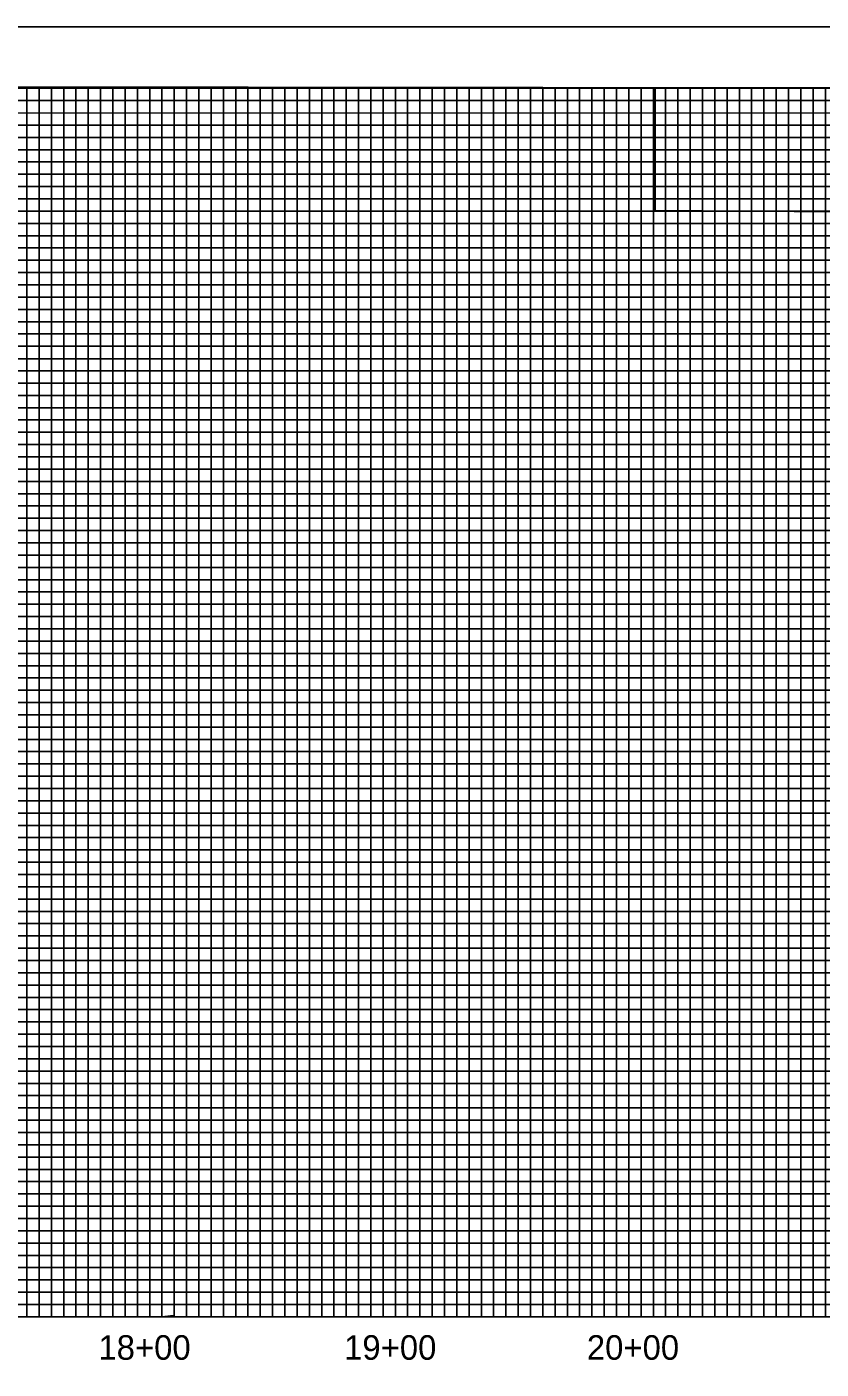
# Model space of a CAD drawing. Extents: x 505602 to 507548, y 483109 to 484209.
# Drawn here: x 506569 to 506892, y 483662 to 484209 of the extents above; entities that cross this region are included whole.
import ezdxf

# ---------------------------------------------------------------- set-up
doc = ezdxf.new("R2010")
doc.units = 0
for name, color, linetype in [('Exist Vertical Profile Vertical Axis Label', 7, 'Continuous'), ('Scratch_Level_5', 7, 'Continuous'), ('Sheet Layout Profile Border Port 1', 7, 'Continuous'), ('Sheet Plot Border Outside CELL', 7, 'Continuous'), ('Sheet Profile CELL', 7, 'Continuous'), ('Sheet Profile Grid Major CELL', 7, 'Continuous'), ('Sheet Profile Grid Middle CELL', 7, 'Continuous'), ('Sheet Profile Grid Minor CELL', 7, 'Continuous')]:
    doc.layers.add(name, color=color, linetype=linetype)

msp = doc.modelspace()

# ---------------------------------------------------------------- linework, layer by layer
at = {"layer": 'Scratch_Level_5'}
msp.add_lwpolyline([(505819.08, 484183.83), (506824.84, 484183.83), (506824.84, 484134), (506919.08, 484133.22), (506919.3, 483683.71), (505819.08, 483683.71)], close=True, dxfattribs=at)
msp.add_lwpolyline([(505819.08, 484022.66), (505819.08, 483683.71), (507219.08, 483683.71), (507219.08, 484022.66)], dxfattribs=at)
at = {"layer": 'Sheet Layout Profile Border Port 1'}
msp.add_lwpolyline([(505819.08, 484185.09), (505819.08, 483683.71), (507019.08, 483683.71), (507019.08, 484183.71), (507019.08, 484183.71), (507019.08, 484183.71)], close=True, dxfattribs=at)
at = {"layer": 'Sheet Plot Border Outside CELL'}
msp.add_lwpolyline([(505602.08, 483108.71), (507286.08, 483108.71), (507286.08, 484208.71), (505602.08, 484208.71)], close=True, dxfattribs=at)
at = {"layer": 'Sheet Profile CELL'}
msp.add_line((505769.08, 483683.71), (507269.08, 483683.71), dxfattribs=at)
msp.add_lwpolyline([(507269.08, 484183.71), (505769.08, 484183.71), (505769.08, 483133.71), (507269.08, 483133.71)], close=True, dxfattribs=at)
at = {"layer": 'Sheet Profile Grid Major CELL'}
for points in [[(506519.08, 483683.71), (506569.08, 483683.71), (506569.08, 484183.71), (506619.08, 484183.71), (506619.08, 483683.71), (506669.08, 483683.71), (506669.08, 484183.71), (506719.08, 484183.71), (506719.08, 483683.71), (506769.08, 483683.71), (506769.08, 484183.71), (506819.08, 484183.71), (506819.08, 483683.71), (506869.08, 483683.71), (506869.08, 484183.71), (506919.08, 484183.71), (506919.08, 483683.71), (506969.08, 483683.71), (506969.08, 484183.71), (507019.08, 484183.71), (507019.08, 483683.71), (507069.08, 483683.71), (507069.08, 484183.71), (507095.38, 484183.71)], [(505769.08, 484133.71), (507069.08, 484133.71)], [(507069.08, 484083.71), (505769.08, 484083.71), (505769.08, 484033.71), (507069.08, 484033.71)], [(507269.08, 483983.71), (505769.08, 483983.71), (505769.08, 483933.71), (507269.08, 483933.71)], [(507269.08, 483883.71), (505769.08, 483883.71), (505769.08, 483833.71), (507269.08, 483833.71)], [(507269.08, 483783.71), (505769.08, 483783.71), (505769.08, 483783.71), (505769.08, 483733.71), (507269.08, 483733.71)]]:
    msp.add_lwpolyline(points, dxfattribs=at)
at = {"layer": 'Sheet Profile Grid Middle CELL'}
msp.add_line((505769.08, 484158.71), (507069.03, 484158.71), dxfattribs=at)
for points in [[(506544.08, 483683.71), (506594.08, 483683.71), (506594.08, 484183.71), (506644.08, 484183.71), (506644.08, 483683.71), (506694.08, 483683.71), (506694.08, 484183.71), (506744.08, 484183.71), (506744.08, 483683.71), (506794.08, 483683.71), (506794.08, 484183.71), (506844.08, 484183.71), (506844.08, 483683.71), (506894.08, 483683.71), (506894.08, 484183.71), (506944.08, 484183.71), (506944.08, 483683.71), (506994.08, 483683.71), (506994.08, 484183.71), (507044.08, 484183.71), (507044.08, 483683.71), (507094.08, 483683.71), (507094.08, 484022.66)], [(507069.08, 484108.71), (505769.08, 484108.71), (505769.08, 484058.71), (507069.08, 484058.71)], [(507269.08, 484008.71), (505769.08, 484008.71), (505769.08, 483958.71), (507094.08, 483958.71)], [(507269.08, 483908.71), (505769.08, 483908.71), (505769.08, 483858.71), (507269.08, 483858.71)], [(507269.08, 483808.71), (505769.08, 483808.71), (505769.08, 483758.71), (507269.08, 483758.71)], [(507269.08, 483708.71), (505769.08, 483708.71)]]:
    msp.add_lwpolyline(points, dxfattribs=at)
at = {"layer": 'Sheet Profile Grid Minor CELL'}
for p, q in [((505819.08, 484178.71), (507069.08, 484178.71)), ((507069.08, 484173.71), (505819.08, 484173.36)), ((505819.08, 484168.71), (507069.08, 484168.71)), ((507069.03, 484048.71), (505819.08, 484048.71)), ((507069.08, 484043.71), (505819.08, 484043.71)), ((507069.08, 484038.71), (505819.08, 484038.71)), ((505819.08, 484028.71), (507069.08, 484028.71)), ((507069.08, 484023.71), (505819.08, 484023.71)), ((505819.08, 484018.71), (507219.08, 484018.71)), ((507219.08, 483998.71), (505819.08, 483998.71)), ((505819.08, 483993.71), (507219.08, 483993.71)), ((507219.08, 483973.71), (505819.08, 483973.71)), ((505819.08, 483968.71), (507219.08, 483968.71)), ((507219.08, 483948.71), (505819.08, 483948.71)), ((505819.08, 483943.71), (507219.08, 483943.71)), ((507219.08, 483938.71), (505819.08, 483938.71)), ((505819.08, 483928.71), (507219.08, 483928.71)), ((507219.08, 483923.71), (505819.08, 483923.71)), ((505819.08, 483918.71), (507219.08, 483918.71)), ((507219.08, 483913.71), (505819.08, 483913.71)), ((505819.08, 483903.71), (507219.08, 483903.71)), ((507219.08, 483898.71), (505819.08, 483898.71)), ((505819.08, 483893.71), (507219.08, 483893.71)), ((507219.08, 483888.71), (505819.08, 483888.71)), ((505819.08, 483878.71), (507219.08, 483878.71)), ((507219.08, 483873.71), (505819.08, 483873.71)), ((505819.08, 483868.71), (507219.08, 483868.71)), ((507219.08, 483863.71), (505819.08, 483863.71)), ((505819.08, 483853.71), (507219.08, 483853.71)), ((507219.08, 483848.71), (505819.08, 483848.71)), ((505819.08, 483843.71), (507219.08, 483843.71)), ((507219.08, 483838.71), (505819.08, 483838.71)), ((505819.08, 483828.71), (507219.08, 483828.71)), ((507219.08, 483823.71), (505819.08, 483823.71)), ((505819.08, 483818.71), (507219.08, 483818.71)), ((507219.08, 483813.71), (505819.08, 483813.71)), ((505819.08, 483803.71), (507219.08, 483803.71)), ((507219.08, 483798.71), (505819.08, 483798.71)), ((507219.08, 483793.71), (505819.08, 483793.71)), ((507219.08, 483788.71), (505819.08, 483788.71)), ((505819.08, 483778.71), (507219.08, 483778.71)), ((507219.08, 483773.71), (505819.08, 483773.71)), ((505819.08, 483768.71), (507219.08, 483768.71)), ((507219.08, 483763.71), (505819.08, 483763.71)), ((505819.08, 483753.71), (507219.08, 483753.71)), ((507219.08, 483748.71), (505819.08, 483748.71)), ((505819.08, 483743.71), (507219.08, 483743.71)), ((507219.08, 483738.71), (505819.08, 483738.71)), ((505819.08, 483728.71), (507219.08, 483728.71)), ((507219.08, 483723.71), (505819.08, 483723.71)), ((505819.08, 483718.71), (507219.08, 483718.71)), ((507219.08, 483713.71), (505819.08, 483713.71)), ((505819.08, 483703.71), (507219.08, 483703.71)), ((507219.08, 483698.71), (505819.08, 483698.71)), ((505819.08, 483693.71), (507219.08, 483693.71))]:
    msp.add_line(p, q, dxfattribs=at)
for points in [[(506564.08, 484183.71), (506574.08, 484183.71), (506574.08, 483683.71), (506579.08, 483683.71), (506579.08, 484183.71), (506584.08, 484183.71), (506584.08, 483683.71), (506589.08, 483683.71), (506589.08, 484183.71), (506599.08, 484183.71), (506599.08, 483683.71), (506604.08, 483683.71), (506604.08, 484183.71), (506609.08, 484183.71), (506609.08, 483683.71), (506614.08, 483683.71), (506614.08, 484183.71), (506624.08, 484183.71), (506624.08, 483683.71), (506628.78, 483684.26), (506629.08, 483683.71), (506629.08, 484183.71), (506634.08, 484183.71), (506634.08, 483683.71), (506639.08, 483683.71), (506639.08, 484183.71), (506649.08, 484183.71), (506649.08, 483683.71), (506654.08, 483683.71)], [(506654.08, 483683.71), (506654.08, 484183.71), (506659.08, 484183.71), (506659.08, 483683.71), (506664.08, 483683.71), (506664.08, 484183.71), (506674.08, 484183.71), (506674.08, 483683.71), (506679.08, 483683.71), (506679.08, 484183.71), (506684.08, 484183.71), (506684.08, 483683.71), (506689.08, 483683.71), (506689.08, 484183.71), (506699.08, 484183.71), (506699.08, 483683.71), (506704.08, 483683.71), (506704.08, 484183.71), (506709.08, 484183.71), (506709.08, 483683.71), (506714.08, 483683.71), (506714.08, 484183.71), (506724.08, 484183.71), (506724.08, 483683.71), (506729.08, 483683.71), (506729.08, 484183.71), (506734.08, 484183.71), (506734.08, 483683.71), (506739.08, 483683.71), (506739.08, 484183.71), (506749.08, 484183.71), (506749.08, 483683.71), (506754.08, 483683.71), (506754.08, 484183.71), (506759.08, 484183.71), (506759.08, 483683.71), (506764.08, 483683.71), (506764.08, 484183.71), (506774.08, 484183.71), (506774.08, 483683.71), (506779.08, 483683.71), (506779.08, 484183.71), (506784.08, 484183.71), (506784.08, 483683.71), (506789.08, 483683.71), (506789.08, 484183.71), (506799.08, 484183.71), (506799.08, 483683.71), (506804.08, 483683.71), (506804.08, 484183.71), (506809.08, 484183.71), (506809.08, 483683.71), (506814.08, 483683.71), (506814.08, 484183.71), (506824.08, 484183.71), (506824.08, 483683.71), (506829.08, 483683.71), (506829.08, 484183.71), (506834.08, 484183.71), (506834.08, 483683.71), (506839.08, 483683.71), (506839.08, 484183.71), (506849.08, 484183.71), (506849.08, 483683.71), (506854.08, 483683.71), (506854.08, 484183.71), (506859.08, 484183.71), (506859.08, 483683.71), (506864.08, 483683.71), (506864.08, 484183.71), (506874.08, 484183.71), (506874.08, 483683.71), (506879.08, 483683.71), (506879.08, 484183.71), (506884.08, 484183.71), (506884.08, 483683.71), (506889.08, 483683.71), (506889.08, 484183.71), (506899.08, 484183.71)], [(507069.08, 484163.71), (505819.08, 484163.71), (505819.08, 484153.71), (507069.08, 484153.71)], [(507069.03, 484148.71), (505819.08, 484148.71), (505819.08, 484143.71), (507069.08, 484143.71)], [(507069.08, 484138.71), (505819.08, 484138.71), (505819.08, 484128.71), (507069.08, 484128.71)], [(507069.08, 484123.71), (505819.08, 484123.71), (505819.08, 484118.71), (507069.08, 484118.71)], [(507069.08, 484113.71), (505819.08, 484113.71), (505819.08, 484103.71), (507069.08, 484103.71)], [(507069.08, 484098.71), (505819.08, 484098.71), (505819.08, 484093.71), (507069.08, 484093.71)], [(507069.08, 484088.71), (505819.08, 484088.71), (505819.08, 484078.71), (507069.08, 484078.71)], [(507069.08, 484073.61), (505819.18, 484073.61), (505819.18, 484068.71), (507069.08, 484068.71)], [(507069.08, 484063.71), (505819.08, 484063.71), (505819.08, 484053.71), (507069.08, 484053.71)], [(507219.08, 484013.71), (505819.08, 484013.71), (505819.08, 484003.71), (507219.08, 484003.71)], [(507219.08, 483988.71), (505819.08, 483988.71), (505819.08, 483978.71), (507219.08, 483978.71)], [(507219.08, 483963.71), (505819.08, 483963.71), (505819.08, 483953.71), (507219.08, 483953.71)], [(507219.08, 483688.71), (505819.08, 483688.71)]]:
    msp.add_lwpolyline(points, dxfattribs=at)

# ---------------------------------------------------------------- texts
at = {"layer": 'Exist Vertical Profile Vertical Axis Label'}
for s, p in [('18+00', (506598.21, 483666.21)), ('19+00', (506698.21, 483666.21)), ('20+00', (506797.01, 483666.21))]:
    msp.add_text(s, height=10, dxfattribs=at).set_placement(p)

doc.saveas('drawing.dxf')
